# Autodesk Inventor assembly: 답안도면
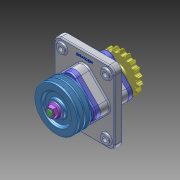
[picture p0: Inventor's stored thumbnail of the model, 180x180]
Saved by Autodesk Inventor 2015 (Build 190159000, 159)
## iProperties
Created: 2026-07
Part Number: 답안도면
Document SubType Name: Assembly
Designer: USER
Author: USER
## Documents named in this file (12)
- C:\Users\USER\Desktop\760705V1003\답안도면.iam
- C:\Users\USER\Desktop\760705V1003\본체.ipt
- C:\Users\USER\Desktop\760705V1003\가져온 구성요소\6각 구멍붙이 볼트 M6x16\6각 구멍붙이 볼트 M6x16.ipt
- C:\Users\USER\Desktop\760705V1003\가져온 구성요소\6각 플랜지 너트 M16\6각 플랜지 너트 M16.ipt
- C:\Users\USER\Desktop\760705V1003\가져온 구성요소\V-벨트풀리\V-벨트풀리.ipt
- C:\Users\USER\Desktop\760705V1003\가져온 구성요소\깊은 홈 볼 베어링 6206\깊은 홈 볼 베어링 6206.ipt
- C:\Users\USER\Desktop\760705V1003\가져온 구성요소\오일 실 30 45 8\오일 실 30 45 8.ipt
- C:\Users\USER\Desktop\760705V1003\가져온 구성요소\체인 스프로킷\체인 스프로킷.ipt
- C:\Users\USER\Desktop\760705V1003\가져온 구성요소\축\축.ipt
- C:\Users\USER\Desktop\760705V1003\가져온 구성요소\칼라\칼라.ipt
- C:\Users\USER\Desktop\760705V1003\가져온 구성요소\커버\커버.ipt
- C:\Users\USER\Desktop\760705V1003\가져온 구성요소\평행 키 6x6x20\평행 키 6x6x20.ipt
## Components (11 placed, 3 different names)
1. 6각 구멍붙이 볼트 M6x16:1
2. 6각 플랜지 너트 M16:1
3. V-벨트풀리:1
4. 6각 플랜지 너트 M16:2
5. 6각 구멍붙이 볼트 M6x16:2
6. 6각 구멍붙이 볼트 M6x16:3
7. 6각 구멍붙이 볼트 M6x16:4
8. 6각 구멍붙이 볼트 M6x16:5
9. 6각 구멍붙이 볼트 M6x16:6
10. 6각 구멍붙이 볼트 M6x16:7
11. 6각 구멍붙이 볼트 M6x16:8
